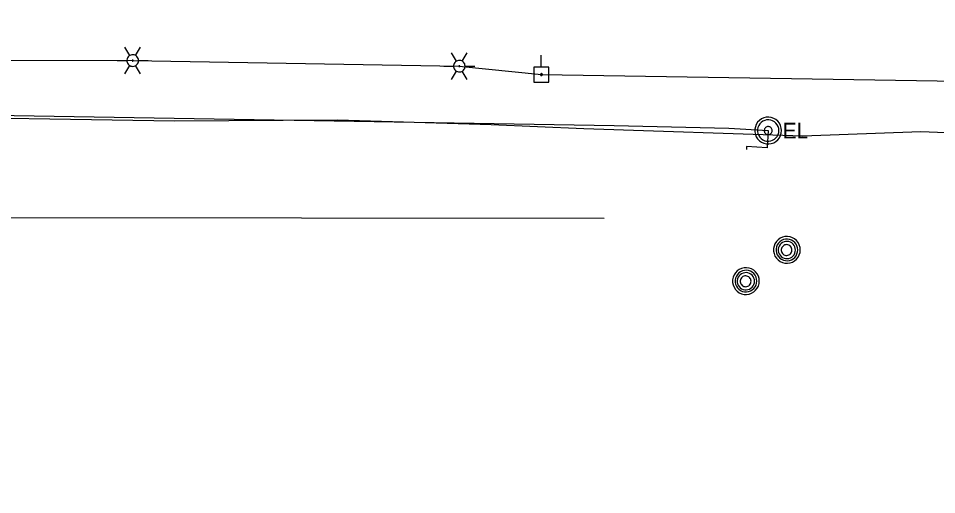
# Model space of a CAD drawing. Extents: x 600849 to 606371, y 330010 to 403088.
# Drawn here: x 605225.1 to 605451.6, y 349867.2 to 349984.7 of the extents above; entities that cross this region are included whole.
import ezdxf

# ---------------------------------------------------------------- set-up
doc = ezdxf.new("R2010")
doc.units = 0
for name, color, linetype in [('E_LTG', 7, 'Continuous'), ('E_UTL_E', 7, 'Continuous'), ('E_UTL_E_UG', 7, 'Continuous'), ('E_UTL_EPowerPole', 7, 'Continuous'), ('E_UTL_G_UG', 7, 'Continuous'), ('E_UTL_MH', 7, 'Continuous'), ('E_UTL_Overhead', 7, 'Continuous'), ('E_UTL_SAN_UG', 7, 'Continuous')]:
    doc.layers.add(name, color=color, linetype=linetype)

msp = doc.modelspace()

# ---------------------------------------------------------------- linework, layer by layer
at = {"layer": 'E_LTG'}
for points in [[(605252.55, 349975.49), (605251.36, 349977.55)], [(605253.98, 349975.49), (605255.17, 349977.55)], [(605254.69, 349974.25), (605254.67, 349974.52), (605254.59, 349974.79), (605254.47, 349975.03), (605254.3, 349975.24), (605254.09, 349975.42), (605253.86, 349975.55), (605253.6, 349975.64), (605253.33, 349975.68), (605253.06, 349975.67), (605252.8, 349975.6), (605252.55, 349975.49), (605252.33, 349975.33), (605252.14, 349975.14), (605251.99, 349974.91), (605251.89, 349974.66), (605251.84, 349974.39), (605251.84, 349974.12), (605251.89, 349973.85), (605251.99, 349973.6), (605252.14, 349973.37), (605252.33, 349973.17), (605252.55, 349973.02), (605252.8, 349972.9), (605253.06, 349972.84), (605253.33, 349972.83), (605253.6, 349972.87), (605253.86, 349972.95), (605254.09, 349973.09), (605254.3, 349973.27), (605254.47, 349973.48), (605254.59, 349973.72), (605254.67, 349973.98), (605254.69, 349974.25)], [(605254.69, 349974.25), (605254.67, 349974.52), (605254.59, 349974.79), (605254.47, 349975.03), (605254.3, 349975.24), (605254.09, 349975.42), (605253.86, 349975.55), (605253.6, 349975.64), (605253.33, 349975.68), (605253.06, 349975.67), (605252.8, 349975.6), (605252.55, 349975.49), (605252.33, 349975.33), (605252.14, 349975.14), (605251.99, 349974.91), (605251.89, 349974.66), (605251.84, 349974.39), (605251.84, 349974.12), (605251.89, 349973.85), (605251.99, 349973.6), (605252.14, 349973.37), (605252.33, 349973.17), (605252.55, 349973.02), (605252.8, 349972.9), (605253.06, 349972.84), (605253.33, 349972.83), (605253.6, 349972.87), (605253.86, 349972.95), (605254.09, 349973.09), (605254.3, 349973.27), (605254.47, 349973.48), (605254.59, 349973.72), (605254.67, 349973.98), (605254.69, 349974.25)], [(605254.69, 349974.25), (605254.67, 349974.52), (605254.59, 349974.79), (605254.47, 349975.03), (605254.3, 349975.24), (605254.09, 349975.42), (605253.86, 349975.55), (605253.6, 349975.64), (605253.33, 349975.68), (605253.06, 349975.67), (605252.8, 349975.6), (605252.55, 349975.49), (605252.33, 349975.33), (605252.14, 349975.14), (605251.99, 349974.91), (605251.89, 349974.66), (605251.84, 349974.39), (605251.84, 349974.12), (605251.89, 349973.85), (605251.99, 349973.6), (605252.14, 349973.37), (605252.33, 349973.17), (605252.55, 349973.02), (605252.8, 349972.9), (605253.06, 349972.84), (605253.33, 349972.83), (605253.6, 349972.87), (605253.86, 349972.95), (605254.09, 349973.09), (605254.3, 349973.27), (605254.47, 349973.48), (605254.59, 349973.72), (605254.67, 349973.98), (605254.69, 349974.25)], [(605333.13, 349974.11), (605331.94, 349976.18)], [(605334.56, 349974.11), (605335.75, 349976.18)], [(605249.45, 349974.25), (605251.84, 349974.25)], [(605251.36, 349970.95), (605252.55, 349973.02)], [(605253.38, 349974.25), (605253.38, 349974.28), (605253.38, 349974.3), (605253.36, 349974.32), (605253.35, 349974.34), (605253.33, 349974.35), (605253.31, 349974.36), (605253.29, 349974.37), (605253.27, 349974.37), (605253.25, 349974.37), (605253.23, 349974.37), (605253.2, 349974.36), (605253.19, 349974.34), (605253.17, 349974.33), (605253.16, 349974.31), (605253.15, 349974.29), (605253.15, 349974.27), (605253.15, 349974.24), (605253.15, 349974.22), (605253.16, 349974.2), (605253.17, 349974.18), (605253.19, 349974.16), (605253.2, 349974.15), (605253.23, 349974.14), (605253.25, 349974.14), (605253.27, 349974.14), (605253.29, 349974.14), (605253.31, 349974.15), (605253.33, 349974.16), (605253.35, 349974.17), (605253.36, 349974.19), (605253.38, 349974.21), (605253.38, 349974.23), (605253.38, 349974.25)], [(605255.17, 349970.95), (605253.98, 349973.02)], [(605254.69, 349974.25), (605257.08, 349974.25)], [(605330.04, 349972.88), (605332.42, 349972.88)], [(605335.28, 349972.88), (605335.25, 349973.15), (605335.17, 349973.41), (605335.05, 349973.65), (605334.88, 349973.86), (605334.68, 349974.04), (605334.44, 349974.18), (605334.19, 349974.26), (605333.92, 349974.3), (605333.64, 349974.29), (605333.38, 349974.23), (605333.13, 349974.11), (605332.91, 349973.96), (605332.73, 349973.76), (605332.58, 349973.53), (605332.48, 349973.28), (605332.43, 349973.01), (605332.43, 349972.74), (605332.48, 349972.47), (605332.58, 349972.22), (605332.73, 349971.99), (605332.91, 349971.8), (605333.13, 349971.64), (605333.38, 349971.53), (605333.64, 349971.46), (605333.92, 349971.45), (605334.19, 349971.49), (605334.44, 349971.58), (605334.68, 349971.71), (605334.88, 349971.89), (605335.05, 349972.1), (605335.17, 349972.34), (605335.25, 349972.61), (605335.28, 349972.88)], [(605335.28, 349972.88), (605335.25, 349973.15), (605335.17, 349973.41), (605335.05, 349973.65), (605334.88, 349973.86), (605334.68, 349974.04), (605334.44, 349974.18), (605334.19, 349974.26), (605333.92, 349974.3), (605333.64, 349974.29), (605333.38, 349974.23), (605333.13, 349974.11), (605332.91, 349973.96), (605332.73, 349973.76), (605332.58, 349973.53), (605332.48, 349973.28), (605332.43, 349973.01), (605332.43, 349972.74), (605332.48, 349972.47), (605332.58, 349972.22), (605332.73, 349971.99), (605332.91, 349971.8), (605333.13, 349971.64), (605333.38, 349971.53), (605333.64, 349971.46), (605333.92, 349971.45), (605334.19, 349971.49), (605334.44, 349971.58), (605334.68, 349971.71), (605334.88, 349971.89), (605335.05, 349972.1), (605335.17, 349972.34), (605335.25, 349972.61), (605335.28, 349972.88)], [(605335.28, 349972.88), (605335.25, 349973.15), (605335.17, 349973.41), (605335.05, 349973.65), (605334.88, 349973.86), (605334.68, 349974.04), (605334.44, 349974.18), (605334.19, 349974.26), (605333.92, 349974.3), (605333.64, 349974.29), (605333.38, 349974.23), (605333.13, 349974.11), (605332.91, 349973.96), (605332.73, 349973.76), (605332.58, 349973.53), (605332.48, 349973.28), (605332.43, 349973.01), (605332.43, 349972.74), (605332.48, 349972.47), (605332.58, 349972.22), (605332.73, 349971.99), (605332.91, 349971.8), (605333.13, 349971.64), (605333.38, 349971.53), (605333.64, 349971.46), (605333.92, 349971.45), (605334.19, 349971.49), (605334.44, 349971.58), (605334.68, 349971.71), (605334.88, 349971.89), (605335.05, 349972.1), (605335.17, 349972.34), (605335.25, 349972.61), (605335.28, 349972.88)], [(605333.97, 349972.88), (605333.97, 349972.9), (605333.96, 349972.92), (605333.95, 349972.94), (605333.93, 349972.96), (605333.92, 349972.97), (605333.9, 349972.98), (605333.88, 349972.99), (605333.85, 349972.99), (605333.83, 349972.99), (605333.81, 349972.99), (605333.79, 349972.98), (605333.77, 349972.97), (605333.75, 349972.95), (605333.74, 349972.93), (605333.73, 349972.91), (605333.73, 349972.89), (605333.73, 349972.86), (605333.73, 349972.84), (605333.74, 349972.82), (605333.75, 349972.8), (605333.77, 349972.79), (605333.79, 349972.77), (605333.81, 349972.76), (605333.83, 349972.76), (605333.85, 349972.76), (605333.88, 349972.76), (605333.9, 349972.77), (605333.92, 349972.78), (605333.93, 349972.79), (605333.95, 349972.81), (605333.96, 349972.83), (605333.97, 349972.85), (605333.97, 349972.88)], [(605335.28, 349972.88), (605337.66, 349972.88)], [(605331.94, 349969.58), (605333.13, 349971.64)], [(605335.75, 349969.58), (605334.56, 349971.64)]]:
    msp.add_lwpolyline(points, dxfattribs=at)
at = {"layer": 'E_UTL_E'}
for points in [[(605413.35, 349956.99), (605413.29, 349957.62), (605413.11, 349958.22), (605412.82, 349958.78), (605412.43, 349959.27), (605411.96, 349959.68), (605411.42, 349959.99), (605410.82, 349960.2), (605410.2, 349960.29), (605409.58, 349960.26), (605408.97, 349960.11), (605408.4, 349959.85), (605407.88, 349959.49), (605407.45, 349959.03), (605407.11, 349958.5), (605406.88, 349957.92), (605406.76, 349957.3), (605406.76, 349956.68), (605406.88, 349956.06), (605407.11, 349955.48), (605407.45, 349954.95), (605407.88, 349954.5), (605408.4, 349954.13), (605408.97, 349953.87), (605409.58, 349953.72), (605410.2, 349953.69), (605410.82, 349953.78), (605411.42, 349953.99), (605411.96, 349954.3), (605412.43, 349954.71), (605412.82, 349955.21), (605413.11, 349955.76), (605413.29, 349956.37), (605413.35, 349956.99)], [(605413.35, 349956.99), (605413.29, 349957.62), (605413.11, 349958.22), (605412.82, 349958.78), (605412.43, 349959.27), (605411.96, 349959.68), (605411.42, 349959.99), (605410.82, 349960.2), (605410.2, 349960.29), (605409.58, 349960.26), (605408.97, 349960.11), (605408.4, 349959.85), (605407.88, 349959.49), (605407.45, 349959.03), (605407.11, 349958.5), (605406.88, 349957.92), (605406.76, 349957.3), (605406.76, 349956.68), (605406.88, 349956.06), (605407.11, 349955.48), (605407.45, 349954.95), (605407.88, 349954.5), (605408.4, 349954.13), (605408.97, 349953.87), (605409.58, 349953.72), (605410.2, 349953.69), (605410.82, 349953.78), (605411.42, 349953.99), (605411.96, 349954.3), (605412.43, 349954.71), (605412.82, 349955.21), (605413.11, 349955.76), (605413.29, 349956.37), (605413.35, 349956.99)], [(605412.69, 349956.99), (605412.64, 349957.49), (605412.5, 349957.97), (605412.27, 349958.42), (605411.96, 349958.81), (605411.58, 349959.14), (605411.14, 349959.39), (605410.67, 349959.56), (605410.17, 349959.63), (605409.67, 349959.6), (605409.18, 349959.49), (605408.73, 349959.28), (605408.32, 349958.99), (605407.97, 349958.62), (605407.7, 349958.2), (605407.51, 349957.74), (605407.42, 349957.24), (605407.42, 349956.74), (605407.51, 349956.25), (605407.7, 349955.78), (605407.97, 349955.36), (605408.32, 349955), (605408.73, 349954.7), (605409.18, 349954.5), (605409.67, 349954.38), (605410.17, 349954.35), (605410.67, 349954.43), (605411.14, 349954.59), (605411.58, 349954.84), (605411.96, 349955.17), (605412.27, 349955.56), (605412.5, 349956.01), (605412.64, 349956.49), (605412.69, 349956.99)], [(605412.69, 349956.99), (605412.64, 349957.49), (605412.5, 349957.97), (605412.27, 349958.42), (605411.96, 349958.81), (605411.58, 349959.14), (605411.14, 349959.39), (605410.67, 349959.56), (605410.17, 349959.63), (605409.67, 349959.6), (605409.18, 349959.49), (605408.73, 349959.28), (605408.32, 349958.99), (605407.97, 349958.62), (605407.7, 349958.2), (605407.51, 349957.74), (605407.42, 349957.24), (605407.42, 349956.74), (605407.51, 349956.25), (605407.7, 349955.78), (605407.97, 349955.36), (605408.32, 349955), (605408.73, 349954.7), (605409.18, 349954.5), (605409.67, 349954.38), (605410.17, 349954.35), (605410.67, 349954.43), (605411.14, 349954.59), (605411.58, 349954.84), (605411.96, 349955.17), (605412.27, 349955.56), (605412.5, 349956.01), (605412.64, 349956.49), (605412.69, 349956.99)], [(605411.04, 349956.99), (605411.02, 349957.18), (605410.96, 349957.36), (605410.88, 349957.53), (605410.76, 349957.67), (605410.62, 349957.8), (605410.46, 349957.89), (605410.28, 349957.95), (605410.09, 349957.98), (605409.9, 349957.97), (605409.72, 349957.93), (605409.55, 349957.85), (605409.4, 349957.74), (605409.27, 349957.6), (605409.17, 349957.44), (605409.1, 349957.27), (605409.06, 349957.09), (605409.06, 349956.9), (605409.1, 349956.71), (605409.17, 349956.54), (605409.27, 349956.38), (605409.4, 349956.24), (605409.55, 349956.13), (605409.72, 349956.06), (605409.9, 349956.01), (605410.09, 349956), (605410.28, 349956.03), (605410.46, 349956.09), (605410.62, 349956.18), (605410.76, 349956.31), (605410.88, 349956.46), (605410.96, 349956.62), (605411.02, 349956.8), (605411.04, 349956.99)], [(605411.04, 349956.99), (605411.02, 349957.18), (605410.96, 349957.36), (605410.88, 349957.53), (605410.76, 349957.67), (605410.62, 349957.8), (605410.46, 349957.89), (605410.28, 349957.95), (605410.09, 349957.98), (605409.9, 349957.97), (605409.72, 349957.93), (605409.55, 349957.85), (605409.4, 349957.74), (605409.27, 349957.6), (605409.17, 349957.44), (605409.1, 349957.27), (605409.06, 349957.09), (605409.06, 349956.9), (605409.1, 349956.71), (605409.17, 349956.54), (605409.27, 349956.38), (605409.4, 349956.24), (605409.55, 349956.13), (605409.72, 349956.06), (605409.9, 349956.01), (605410.09, 349956), (605410.28, 349956.03), (605410.46, 349956.09), (605410.62, 349956.18), (605410.76, 349956.31), (605410.88, 349956.46), (605410.96, 349956.62), (605411.02, 349956.8), (605411.04, 349956.99)]]:
    msp.add_lwpolyline(points, dxfattribs=at)
at = {"layer": 'E_UTL_E_UG'}
for points in [[(605179.55, 349961.42), (605372.08, 349958.25), (605400.36, 349957.61), (605410.04, 349956.99)], [(605410.04, 349956.99), (605409.76, 349952.75), (605404.7, 349953.08), (605404.73, 349952.31)]]:
    msp.add_lwpolyline(points, dxfattribs=at)
at = {"layer": 'E_UTL_EPowerPole'}
for points in [[(605354.07, 349972.64), (605354.07, 349975.55)], [(605355.92, 349972.64), (605352.23, 349972.64)], [(605352.23, 349972.64), (605352.23, 349968.95)], [(605355.92, 349968.95), (605355.92, 349972.64)], [(605354.34, 349970.8), (605354.34, 349970.84), (605354.33, 349970.88), (605354.31, 349970.92), (605354.28, 349970.96), (605354.24, 349970.99), (605354.21, 349971.01), (605354.16, 349971.03), (605354.12, 349971.03), (605354.07, 349971.03), (605354.03, 349971.02), (605353.99, 349971), (605353.95, 349970.98), (605353.92, 349970.94), (605353.89, 349970.91), (605353.88, 349970.86), (605353.87, 349970.82), (605353.87, 349970.77), (605353.88, 349970.73), (605353.89, 349970.69), (605353.92, 349970.65), (605353.95, 349970.62), (605353.99, 349970.59), (605354.03, 349970.57), (605354.07, 349970.56), (605354.12, 349970.56), (605354.16, 349970.56), (605354.21, 349970.58), (605354.24, 349970.6), (605354.28, 349970.63), (605354.31, 349970.67), (605354.33, 349970.71), (605354.34, 349970.75), (605354.34, 349970.8)], [(605352.23, 349968.95), (605355.92, 349968.95)]]:
    msp.add_lwpolyline(points, dxfattribs=at)
at = {"layer": 'E_UTL_G_UG'}
msp.add_lwpolyline([(605125.36, 349984.66), (605132.76, 349976.09), (605134.48, 349968.17), (605144.96, 349966.51), (605151.71, 349967.53), (605160.9, 349967.35), (605168.14, 349965.2), (605171.97, 349962.5), (605191.69, 349960.55), (605263.6, 349959.38), (605303.77, 349959.62), (605341.69, 349958.47), (605364.55, 349957.47), (605418.62, 349955.69), (605447.68, 349956.73), (605494.96, 349954.84), (605495.12, 349948.44), (605505.72, 349947.87), (605505.71, 349947.88), (605548.57, 349947.39), (605561.02, 349949.8), (605573.83, 349948.32), (605583.22, 349947.39), (605623.72, 349945.45)], dxfattribs=at)
at = {"layer": 'E_UTL_MH'}
for points in [[(605417.95, 349927.57), (605417.9, 349928.19), (605417.72, 349928.79), (605417.43, 349929.35), (605417.04, 349929.84), (605416.57, 349930.25), (605416.03, 349930.57), (605415.43, 349930.77), (605414.81, 349930.86), (605414.19, 349930.83), (605413.58, 349930.68), (605413, 349930.42), (605412.49, 349930.06), (605412.06, 349929.61), (605411.72, 349929.08), (605411.49, 349928.5), (605411.37, 349927.88), (605411.37, 349927.25), (605411.49, 349926.64), (605411.72, 349926.05), (605412.06, 349925.53), (605412.49, 349925.07), (605413, 349924.71), (605413.58, 349924.45), (605414.19, 349924.3), (605414.81, 349924.27), (605415.43, 349924.36), (605416.03, 349924.56), (605416.57, 349924.88), (605417.04, 349925.29), (605417.43, 349925.78), (605417.72, 349926.34), (605417.9, 349926.94), (605417.95, 349927.57)], [(605417.34, 349927.56), (605417.29, 349928.07), (605417.15, 349928.56), (605416.91, 349929.01), (605416.6, 349929.41), (605416.22, 349929.74), (605415.77, 349930), (605415.29, 349930.16), (605414.79, 349930.23), (605414.28, 349930.21), (605413.79, 349930.09), (605413.32, 349929.88), (605412.91, 349929.58), (605412.56, 349929.22), (605412.28, 349928.79), (605412.09, 349928.32), (605412, 349927.82), (605412, 349927.31), (605412.09, 349926.81), (605412.28, 349926.33), (605412.56, 349925.91), (605412.91, 349925.54), (605413.32, 349925.24), (605413.79, 349925.03), (605414.28, 349924.91), (605414.79, 349924.89), (605415.29, 349924.96), (605415.77, 349925.13), (605416.22, 349925.38), (605416.6, 349925.71), (605416.91, 349926.11), (605417.15, 349926.57), (605417.29, 349927.05), (605417.34, 349927.56)], [(605416.78, 349927.53), (605416.74, 349927.94), (605416.62, 349928.32), (605416.44, 349928.68), (605416.19, 349929), (605415.88, 349929.27), (605415.53, 349929.47), (605415.15, 349929.6), (605414.75, 349929.66), (605414.34, 349929.64), (605413.95, 349929.54), (605413.58, 349929.38), (605413.25, 349929.14), (605412.97, 349928.85), (605412.75, 349928.51), (605412.6, 349928.13), (605412.53, 349927.73), (605412.53, 349927.33), (605412.6, 349926.93), (605412.75, 349926.56), (605412.97, 349926.22), (605413.25, 349925.92), (605413.58, 349925.69), (605413.95, 349925.52), (605414.34, 349925.42), (605414.75, 349925.41), (605415.15, 349925.46), (605415.53, 349925.6), (605415.88, 349925.8), (605416.19, 349926.06), (605416.44, 349926.38), (605416.62, 349926.74), (605416.74, 349927.13), (605416.78, 349927.53)], [(605415.92, 349927.52), (605415.9, 349927.77), (605415.83, 349928.01), (605415.71, 349928.24), (605415.55, 349928.44), (605415.36, 349928.6), (605415.14, 349928.73), (605414.9, 349928.81), (605414.65, 349928.85), (605414.4, 349928.84), (605414.15, 349928.78), (605413.92, 349928.67), (605413.72, 349928.52), (605413.54, 349928.34), (605413.41, 349928.13), (605413.31, 349927.89), (605413.26, 349927.64), (605413.26, 349927.39), (605413.31, 349927.14), (605413.41, 349926.91), (605413.54, 349926.69), (605413.72, 349926.51), (605413.92, 349926.36), (605414.15, 349926.26), (605414.4, 349926.2), (605414.65, 349926.19), (605414.9, 349926.22), (605415.14, 349926.31), (605415.36, 349926.43), (605415.55, 349926.6), (605415.71, 349926.8), (605415.83, 349927.02), (605415.9, 349927.26), (605415.92, 349927.52)], [(605407.86, 349919.87), (605407.8, 349920.49), (605407.62, 349921.09), (605407.33, 349921.65), (605406.95, 349922.14), (605406.47, 349922.55), (605405.93, 349922.87), (605405.34, 349923.07), (605404.71, 349923.16), (605404.09, 349923.13), (605403.48, 349922.98), (605402.91, 349922.72), (605402.4, 349922.36), (605401.96, 349921.91), (605401.62, 349921.38), (605401.39, 349920.8), (605401.27, 349920.18), (605401.27, 349919.55), (605401.39, 349918.94), (605401.62, 349918.35), (605401.96, 349917.83), (605402.4, 349917.37), (605402.91, 349917.01), (605403.48, 349916.75), (605404.09, 349916.6), (605404.71, 349916.57), (605405.34, 349916.66), (605405.93, 349916.86), (605406.47, 349917.18), (605406.95, 349917.59), (605407.33, 349918.08), (605407.62, 349918.64), (605407.8, 349919.24), (605407.86, 349919.87)], [(605407.24, 349919.86), (605407.19, 349920.37), (605407.05, 349920.86), (605406.82, 349921.31), (605406.5, 349921.71), (605406.12, 349922.04), (605405.68, 349922.3), (605405.2, 349922.46), (605404.69, 349922.53), (605404.18, 349922.51), (605403.69, 349922.39), (605403.23, 349922.18), (605402.81, 349921.88), (605402.46, 349921.52), (605402.19, 349921.09), (605402, 349920.62), (605401.9, 349920.12), (605401.9, 349919.61), (605402, 349919.11), (605402.19, 349918.63), (605402.46, 349918.21), (605402.81, 349917.84), (605403.23, 349917.54), (605403.69, 349917.33), (605404.18, 349917.21), (605404.69, 349917.19), (605405.2, 349917.26), (605405.68, 349917.43), (605406.12, 349917.68), (605406.5, 349918.01), (605406.82, 349918.41), (605407.05, 349918.87), (605407.19, 349919.35), (605407.24, 349919.86)], [(605406.68, 349919.83), (605406.64, 349920.24), (605406.53, 349920.62), (605406.34, 349920.98), (605406.09, 349921.3), (605405.78, 349921.57), (605405.43, 349921.77), (605405.05, 349921.9), (605404.65, 349921.96), (605404.25, 349921.94), (605403.85, 349921.84), (605403.48, 349921.68), (605403.16, 349921.44), (605402.88, 349921.15), (605402.66, 349920.81), (605402.51, 349920.43), (605402.43, 349920.03), (605402.43, 349919.63), (605402.51, 349919.23), (605402.66, 349918.86), (605402.88, 349918.52), (605403.16, 349918.22), (605403.48, 349917.99), (605403.85, 349917.82), (605404.25, 349917.72), (605404.65, 349917.71), (605405.05, 349917.76), (605405.43, 349917.9), (605405.78, 349918.1), (605406.09, 349918.36), (605406.34, 349918.68), (605406.53, 349919.04), (605406.64, 349919.43), (605406.68, 349919.83)], [(605405.82, 349919.82), (605405.8, 349920.07), (605405.73, 349920.31), (605405.61, 349920.54), (605405.45, 349920.74), (605405.26, 349920.9), (605405.04, 349921.03), (605404.81, 349921.11), (605404.55, 349921.15), (605404.3, 349921.14), (605404.06, 349921.08), (605403.83, 349920.97), (605403.62, 349920.82), (605403.44, 349920.64), (605403.31, 349920.43), (605403.21, 349920.19), (605403.17, 349919.94), (605403.17, 349919.69), (605403.21, 349919.44), (605403.31, 349919.21), (605403.44, 349918.99), (605403.62, 349918.81), (605403.83, 349918.66), (605404.06, 349918.56), (605404.3, 349918.5), (605404.55, 349918.49), (605404.81, 349918.52), (605405.04, 349918.61), (605405.26, 349918.73), (605405.45, 349918.9), (605405.61, 349919.1), (605405.73, 349919.32), (605405.8, 349919.56), (605405.82, 349919.82)]]:
    msp.add_lwpolyline(points, dxfattribs=at)
at = {"layer": 'E_UTL_Overhead'}
msp.add_lwpolyline([(605143.81, 349749.74), (605140.32, 349817.89), (605154.01, 349974.42), (605253.26, 349974.25), (605333.85, 349972.88), (605354.11, 349970.8), (605513.44, 349968.29), (605659.83, 349966.5)], dxfattribs=at)
at = {"layer": 'E_UTL_SAN_UG'}
msp.add_lwpolyline([(605145.58, 349935.6), (605369.59, 349935.38)], dxfattribs=at)

# ---------------------------------------------------------------- texts
at = {"layer": 'E_UTL_E'}
msp.add_text('EL', height=3.849, dxfattribs=at).set_placement((605413.61, 349955.05))
msp.add_text('EL', height=3.849, dxfattribs=at).set_placement((605413.61, 349955.05))

doc.saveas('drawing.dxf')
